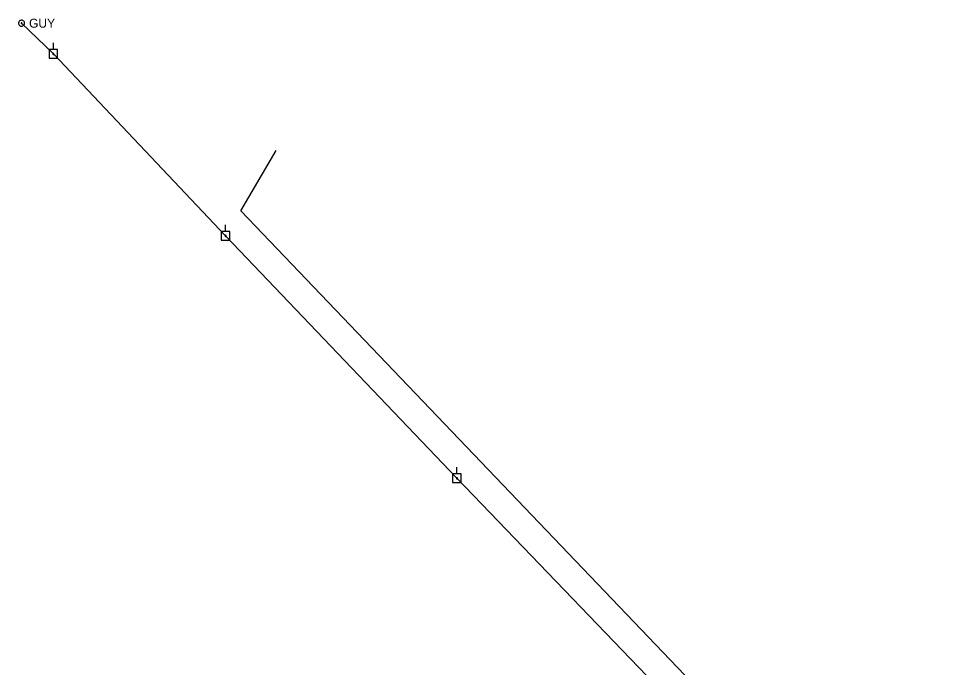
# Model space of a CAD drawing. Extents: x 596028 to 606371, y 330010 to 403088.
# Drawn here: x 596027.7 to 596426.2, y 343577.5 to 343855.6 of the extents above; entities that cross this region are included whole.
import ezdxf

# ---------------------------------------------------------------- set-up
doc = ezdxf.new("R2010")
doc.units = 0
for name, color, linetype in [('E_UTL_E_UG', 7, 'Continuous'), ('E_UTL_EGuyWire', 7, 'Continuous'), ('E_UTL_EPowerPole', 7, 'Continuous'), ('E_UTL_Overhead', 7, 'Continuous')]:
    doc.layers.add(name, color=color, linetype=linetype)

msp = doc.modelspace()

# ---------------------------------------------------------------- linework, layer by layer
at = {"layer": 'E_UTL_E_UG'}
msp.add_lwpolyline([(596419.24, 343463.3), (596122.93, 343773.15), (596138.14, 343799.06)], dxfattribs=at)
at = {"layer": 'E_UTL_EGuyWire'}
msp.add_line((596042.62, 343840.48), (596028.97, 343853.63), dxfattribs=at)
for points in [[(596030.25, 343853.63), (596030.23, 343853.88), (596030.16, 343854.11), (596030.05, 343854.33), (596029.9, 343854.52), (596029.71, 343854.68), (596029.5, 343854.8), (596029.27, 343854.88), (596029.03, 343854.92), (596028.79, 343854.9), (596028.55, 343854.85), (596028.33, 343854.75), (596028.13, 343854.6), (596027.96, 343854.43), (596027.83, 343854.22), (596027.74, 343854), (596027.69, 343853.76), (596027.69, 343853.51), (596027.74, 343853.27), (596027.83, 343853.05), (596027.96, 343852.84), (596028.13, 343852.66), (596028.33, 343852.52), (596028.55, 343852.42), (596028.79, 343852.36), (596029.03, 343852.35), (596029.27, 343852.39), (596029.5, 343852.47), (596029.71, 343852.59), (596029.9, 343852.75), (596030.05, 343852.94), (596030.16, 343853.16), (596030.23, 343853.39), (596030.25, 343853.63)], [(596029.13, 343853.63), (596029.13, 343853.66), (596029.12, 343853.69), (596029.1, 343853.72), (596029.09, 343853.74), (596029.06, 343853.76), (596029.04, 343853.78), (596029.01, 343853.79), (596028.98, 343853.79), (596028.95, 343853.79), (596028.92, 343853.79), (596028.89, 343853.77), (596028.86, 343853.76), (596028.84, 343853.73), (596028.83, 343853.71), (596028.82, 343853.68), (596028.81, 343853.65), (596028.81, 343853.62), (596028.82, 343853.59), (596028.83, 343853.56), (596028.84, 343853.53), (596028.86, 343853.51), (596028.89, 343853.5), (596028.92, 343853.48), (596028.95, 343853.48), (596028.98, 343853.47), (596029.01, 343853.48), (596029.04, 343853.49), (596029.06, 343853.5), (596029.09, 343853.52), (596029.1, 343853.55), (596029.12, 343853.57), (596029.13, 343853.6), (596029.13, 343853.63)]]:
    msp.add_lwpolyline(points, dxfattribs=at)
at = {"layer": 'E_UTL_EPowerPole'}
for points in [[(596044.43, 343842.33), (596040.74, 343842.33)], [(596040.74, 343842.33), (596040.74, 343838.64)], [(596042.58, 343842.33), (596042.58, 343845.24)], [(596044.43, 343838.64), (596044.43, 343842.33)], [(596040.74, 343838.64), (596044.43, 343838.64)], [(596042.86, 343840.48), (596042.85, 343840.53), (596042.84, 343840.57), (596042.82, 343840.61), (596042.79, 343840.65), (596042.76, 343840.68), (596042.72, 343840.7), (596042.67, 343840.72), (596042.63, 343840.72), (596042.58, 343840.72), (596042.54, 343840.71), (596042.5, 343840.69), (596042.46, 343840.66), (596042.43, 343840.63), (596042.41, 343840.59), (596042.39, 343840.55), (596042.38, 343840.51), (596042.38, 343840.46), (596042.39, 343840.42), (596042.41, 343840.37), (596042.43, 343840.34), (596042.46, 343840.3), (596042.5, 343840.28), (596042.54, 343840.26), (596042.58, 343840.25), (596042.63, 343840.25), (596042.67, 343840.25), (596042.72, 343840.27), (596042.76, 343840.29), (596042.79, 343840.32), (596042.82, 343840.36), (596042.84, 343840.4), (596042.85, 343840.44), (596042.86, 343840.48)], [(596116.37, 343764.33), (596116.37, 343767.24)], [(596118.22, 343764.33), (596114.53, 343764.33)], [(596114.53, 343764.33), (596114.53, 343760.64)], [(596116.64, 343762.49), (596116.64, 343762.54), (596116.63, 343762.58), (596116.61, 343762.62), (596116.58, 343762.66), (596116.54, 343762.69), (596116.5, 343762.71), (596116.46, 343762.72), (596116.42, 343762.73), (596116.37, 343762.73), (596116.33, 343762.72), (596116.29, 343762.7), (596116.25, 343762.67), (596116.22, 343762.64), (596116.19, 343762.6), (596116.18, 343762.56), (596116.17, 343762.51), (596116.17, 343762.47), (596116.18, 343762.42), (596116.19, 343762.38), (596116.22, 343762.34), (596116.25, 343762.31), (596116.29, 343762.29), (596116.33, 343762.27), (596116.37, 343762.26), (596116.42, 343762.25), (596116.46, 343762.26), (596116.5, 343762.28), (596116.54, 343762.3), (596116.58, 343762.33), (596116.61, 343762.36), (596116.63, 343762.4), (596116.64, 343762.45), (596116.64, 343762.49)], [(596118.22, 343760.64), (596118.22, 343764.33)], [(596114.53, 343760.64), (596118.22, 343760.64)], [(596215.5, 343660.45), (596215.5, 343663.36)], [(596217.34, 343660.45), (596213.65, 343660.45)], [(596213.65, 343660.45), (596213.65, 343656.76)], [(596215.77, 343658.6), (596215.76, 343658.65), (596215.75, 343658.69), (596215.73, 343658.73), (596215.7, 343658.77), (596215.67, 343658.8), (596215.63, 343658.82), (596215.58, 343658.84), (596215.54, 343658.84), (596215.49, 343658.84), (596215.45, 343658.83), (596215.41, 343658.81), (596215.37, 343658.79), (596215.34, 343658.75), (596215.32, 343658.71), (596215.3, 343658.67), (596215.29, 343658.63), (596215.29, 343658.58), (596215.3, 343658.54), (596215.32, 343658.5), (596215.34, 343658.46), (596215.37, 343658.42), (596215.41, 343658.4), (596215.45, 343658.38), (596215.49, 343658.37), (596215.54, 343658.37), (596215.58, 343658.37), (596215.63, 343658.39), (596215.67, 343658.41), (596215.7, 343658.44), (596215.73, 343658.48), (596215.75, 343658.52), (596215.76, 343658.56), (596215.77, 343658.6)], [(596217.34, 343656.76), (596217.34, 343660.45)], [(596213.65, 343656.76), (596217.34, 343656.76)]]:
    msp.add_lwpolyline(points, dxfattribs=at)
at = {"layer": 'E_UTL_Overhead'}
msp.add_lwpolyline([(596907.13, 342499.57), (596872.87, 342572.96), (596807.17, 342701.41), (596752.6, 342808.68), (596696.55, 342921.05), (596669.38, 342971.18), (596598.89, 343101.31), (596520.59, 343214.94), (596433.09, 343338.93), (596392.19, 343473.17), (596318.24, 343551.79), (596215.53, 343658.6), (596116.41, 343762.49), (596042.62, 343840.48)], dxfattribs=at)

# ---------------------------------------------------------------- texts
at = {"layer": 'E_UTL_EGuyWire'}
msp.add_text('GUY', height=3.85, rotation=360, dxfattribs=at).set_placement((596032.18, 343851.71))

doc.saveas('drawing.dxf')
